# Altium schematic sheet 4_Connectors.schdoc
size 309 x 223 mm; Symbol: Artery_A4; Device: Artery_A4; Company: Artery Technology; Drawed: SD; Version: 1.2; Page Size: A4; @Project Name: AT_START_F403A_V1.2; @Page Count: 4; @Update Date: 2023-09-07; @Create Date: 2023-08-15; @Schematic Name: AT_START_F403A; @Page No: 4; @Page Name: Connectors
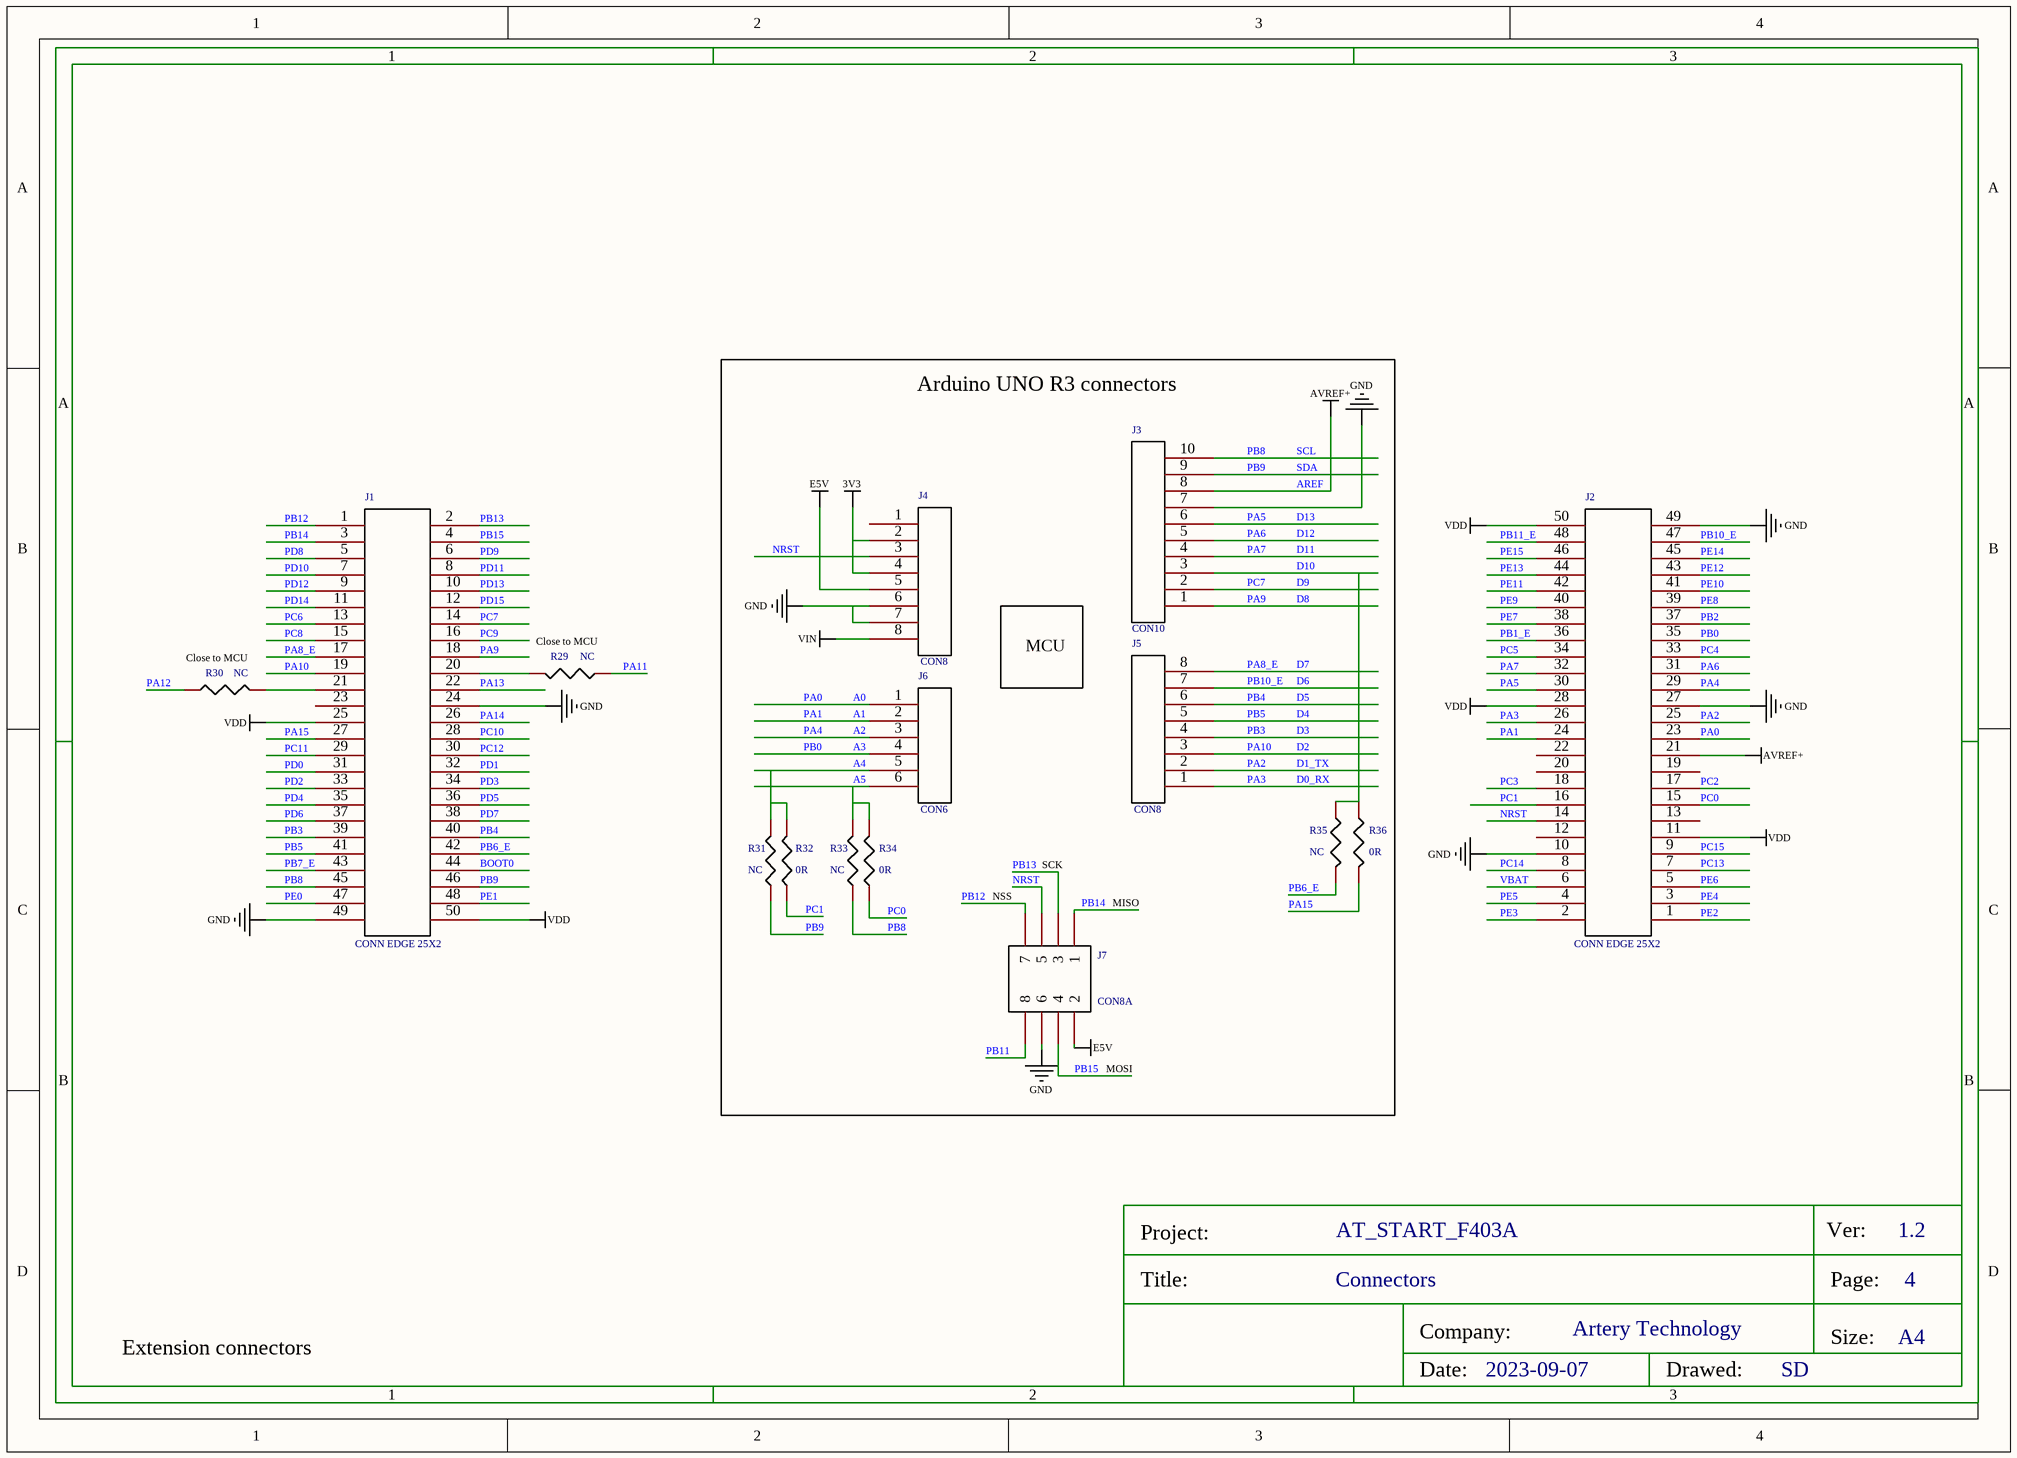
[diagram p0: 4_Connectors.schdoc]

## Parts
J1  CONN EDGE 25X2  [HEAD2*25]
J2  CONN EDGE 25X2  [HEAD2*25]
J3  CON10  [HDR1X10 - 2#]
J4  CON8  [HDR1X8 - 2#]
J5  CON8  [HDR1X8 - 2#]
J6  CON6  [HDR1X6 -2#]
J7  CON8A  [HDR2X4]
R29  NC  [SB-PAD]
R30  NC  [SB-PAD]
R31  NC  [SB-PAD]
R32  0R  [SB-PAD]
R33  NC  [SB-PAD]
R34  0R  [SB-PAD]
R35  NC  [SB-PAD]
R36  0R  [SB-PAD]

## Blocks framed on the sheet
Arduino UNO R3 connectors: J3-J7 R31-R36

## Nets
3V3: J4.2 J4.4
AREF: J2.21 J3.8  [also labelled AVREF+]
E5V: J4.5 J7.2
GND: J1.24 J1.49 J2.10 J2.27 J2.49 J3.7 J4.6 J4.7 J7.6
VDD: J1.25 J1.50 J2.11 J2.28 J2.50
VIN: J4.8
A0: J2.23 J6.1  [also labelled PA0]
A1: J2.24 J6.2  [also labelled PA1]
A2: J2.29 J6.3  [also labelled PA4]
A3: J2.35 J6.4  [also labelled PB0]
A4: J6.5 R31.2 R32.2
A5: J6.6 R33.2 R34.2
BOOT0: J1.44
D0_RX: J2.26 J5.1  [also labelled PA3]
D1_TX: J2.25 J5.2  [also labelled PA2]
D2: J1.19 J5.3  [also labelled PA10]
D3: J1.39 J5.4  [also labelled PB3]
D4: J1.41 J5.5  [also labelled PB5]
D5: J1.40 J5.6  [also labelled PB4]
D6: J2.47 J5.7  [also labelled PB10_E]
D7: J1.17 J5.8  [also labelled PA8_E]
D8: J1.18 J3.1  [also labelled PA9]
D9: J1.14 J3.2  [also labelled PC7]
D10: J3.3 R35.1 R36.1
D11: J2.32 J3.4  [also labelled PA7]
D12: J2.31 J3.5  [also labelled PA6]
D13: J2.30 J3.6  [also labelled PA5]
NRST: J2.14 J4.3 J7.5
PA11: R29.1
PA12: R30.1
PA13: J1.22
PA14: J1.26
PA15: J1.27 R36.2
PB1_E: J2.36
PB2: J2.37
PB6_E: J1.42 R35.2
PB7_E: J1.43
PB8: J1.45 J3.10 R33.1  [also labelled SCL]
PB9: J1.46 J3.9 R31.1  [also labelled SDA]
PB11: J7.8
PB11_E: J2.48
PB12: J1.1 J7.7
PB13: J1.2 J7.3
PB14: J1.3 J7.1
PB15: J1.4 J7.4
PC0: J2.15 R34.1
PC1: J2.16 R32.1
PC2: J2.17
PC3: J2.18
PC4: J2.33
PC5: J2.34
PC6: J1.13
PC8: J1.15
PC9: J1.16
PC10: J1.28
PC11: J1.29
PC12: J1.30
PC13: J2.7
PC14: J2.8
PC15: J2.9
PD0: J1.31
PD1: J1.32
PD2: J1.33
PD3: J1.34
PD4: J1.35
PD5: J1.36
PD6: J1.37
PD7: J1.38
PD8: J1.5
PD9: J1.6
PD10: J1.7
PD11: J1.8
PD12: J1.9
PD13: J1.10
PD14: J1.11
PD15: J1.12
PE0: J1.47
PE1: J1.48
PE2: J2.1
PE3: J2.2
PE4: J2.3
PE5: J2.4
PE6: J2.5
PE7: J2.38
PE8: J2.39
PE9: J2.40
PE10: J2.41
PE11: J2.42
PE12: J2.43
PE13: J2.44
PE14: J2.45
PE15: J2.46
VBAT: J2.6
NetJ1_20: J1.20 R29.2
NetJ1_21: J1.21 R30.2

Not connected (* = marked no-connect by the designer): J1 23; J2 12 13 19 20 22; J4 1

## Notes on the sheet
- (near R30) Close to MCU
- (near R29) Close to MCU
- MCU
- (near J7) NSS
- SCK
- (near J7) MISO
- (near J7) MOSI
- Extension connectors

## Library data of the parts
J1 J2 = CONN EDGE 25X2: Add into BOM: yes
J3 = CON10: Symbol: CON10_0; Add into BOM: yes
J4 J5 = CON8: Add into BOM: yes
J6 = CON6: Add into BOM: yes
J7 = CON8A: Header, 4-Pin, Dual row; Symbol: Header 4X2; Add into BOM: yes
R29 R30 = NC: Symbol: 470,1/10W,1%,SMD0603; Add into BOM: yes
R31 R33 R35 = NC: Symbol: 10K,1/10W,1%,SMD0603_Dup1; Add into BOM: yes
R32 R34 R36 = 0R: Symbol: 10K,1/10W,1%,SMD0603_Dup1; Add into BOM: yes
